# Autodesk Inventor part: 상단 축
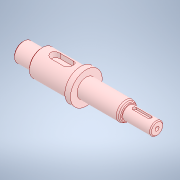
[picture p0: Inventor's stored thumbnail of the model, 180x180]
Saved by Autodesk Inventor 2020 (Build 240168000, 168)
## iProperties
Created: 2024-05
Part Number: 상단 축
Material: 강철, 탄소
Document SubType Name: Modeling
Designer: oem
Density: 7.85 g/cm^3
Appearance: 기본값
Author: jhkim
Sending System: Autodesk Inventor 2025
Preprocessor: ST-DEVELOPER v20
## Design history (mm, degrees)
node "상단 축1"
node "솔리드2"
node "솔리드1"
